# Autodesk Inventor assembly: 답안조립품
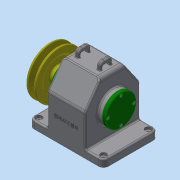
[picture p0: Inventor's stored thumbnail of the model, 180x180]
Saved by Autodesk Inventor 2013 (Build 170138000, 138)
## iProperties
Created: 2016-12
Part Number: 답안조립품
Document SubType Name: Assembly
Designer: dgall
Author: dgall
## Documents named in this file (15)
- C:\Users\dgall\Desktop\461207V1013\답안조립품.iam
- C:\Users\dgall\Desktop\461207V1013\V-벨트풀리.ipt
- C:\Users\dgall\Desktop\461207V1013\뒤커버.ipt
- C:\Users\dgall\Desktop\461207V1013\멈춤나사 - M4x10.ipt
- C:\Users\dgall\Desktop\461207V1013\베어링 6203.ipt
- C:\Users\dgall\Desktop\461207V1013\본체.ipt
- C:\Users\dgall\Desktop\461207V1013\볼트 M3 x 8.ipt
- C:\Users\dgall\Desktop\461207V1013\볼트 M3 x 10.ipt
- C:\Users\dgall\Desktop\461207V1013\부시.ipt
- C:\Users\dgall\Desktop\461207V1013\스퍼기어.ipt
- C:\Users\dgall\Desktop\461207V1013\앞커버.ipt
- C:\Users\dgall\Desktop\461207V1013\오일씰 28 40 8.ipt
- C:\Users\dgall\Desktop\461207V1013\축.ipt
- C:\Users\dgall\Desktop\461207V1013\키 - 5 x 5 x 18.ipt
- C:\Users\dgall\Desktop\461207V1013\키 - 6 x 6 x 22.ipt
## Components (9 placed, 3 different names)
1. V-벨트풀리:1 — 각도:4
2. ISO 4762 M3 x 8:1
3. ISO 4762 M3 x 8:2
4. ISO 4762 M3 x 8:3
5. ISO 4762 M3 x 8:4
6. ISO 4762 M3 x 10:1
7. ISO 4762 M3 x 10:2
8. ISO 4762 M3 x 10:3
9. ISO 4762 M3 x 10:4
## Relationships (1: Angle 1)
- 각도:4 [Angle]: V-벨트풀리:1
